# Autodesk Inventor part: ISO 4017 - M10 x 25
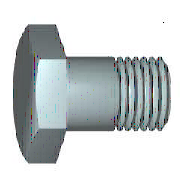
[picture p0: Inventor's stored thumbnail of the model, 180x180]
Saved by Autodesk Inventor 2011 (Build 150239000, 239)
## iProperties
IsCustomPart: 0
Created: 2009-02
Part Number: ISO 4017 - M10 x 25
Material: Stainless Steel, 440C
Description: Hexagon head screws
Document SubType Name: Modeling
Standard: ISO 4017
Designer: 904Chiaki
Standard Revision: Third edition 1999-08-15
Standards Organization: ISO
Language: en-US
Size Designation: M10 x 25
Categories: <MemberInstance><Categories><Category DisplayName="Fasteners" InternalName="e4da775c-781d-43d5-af7c-5136215cf5a6" Mnemonic="FSTN"><Category DisplayName="Bolts"
Density: 7.75 g/cm^3
Mass: 25.8332 g
Surface Area: 15.4943 cm^2
Volume: 3.33332 cm^3
Author: 904Chiaki
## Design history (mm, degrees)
body "Solid1"
workplane "Work Plane1"
revolve "Body" stored, may be unused: angle "d12" = 90 deg
sketch "Sketch2"
  geometry: L1 (0, 9.238)-(8, 4.619); L2 (8, 4.619)-(8, -4.619); L3 (8, -4.619)-(0, -9.238); L4 (0, -9.238)-(-8, -4.619); L5 (-8, -4.619)-(-8, 4.619); L6 (-8, 4.619)-(0, 9.238); 2 further points
  constraints: 12 end point, 1 coincident, 1 vertical, 11 other
  dimensions: "d11" = 16 distance between parallel lines of L5 L2 (= SW)
extrude "Head" join sketch "Sketch2" distance "d3" = 5.8 (= KOH - SD); taper "d4" = 0 deg
revolve "Chamfer1" stored, may be unused: angle "d21" = 90 deg
feature "Thread" dims "d15" = 20.5 (= GEL), "d16" = 0
chamfer "Chamfer2" distance "d6" = 0.92018 (= -0.5 x SPD + 0.5 x GD); stored, may be unused: second distance "d7" = 0.92028 (computed from GUL), angle "d55" = 45 deg
sketch "Sketch1"
  geometry: L1 (0, 7.315)-(0, 5); L2 (4.5, 5)-(25, 5); L3 (25, 5)-(25, 0); L4 (25, 0)-(-0.6, 0); L5 (-5.72, 0)-(30.12, 0) reference; L6 (-0.6, 0)-(-0.6, 7.315); L7 (-0.6, 7.315)-(0, 7.315); L8 (4.5, 5)-(3.58, 5); L9 (3.58, 5)-(0, 5); L10 (0, -1.463)-(0, 8.778) reference
  constraints: 16 end point, 2 collinear, 2 perpendicular, 1 parallel
  dimensions: "d0" = 25 distance between parallel lines of L3 L1 (= NLG); "d1" = 20.5 distance from line of L2.start L3 (= GEL); "d2" = 10 diameter of L2 L4 (= GD); "d9" = 0.6001 distance between parallel lines of L6 L1 (computed from SD); "d10" = 14.63 diameter of L7 L4 (= SD2); "d13" = 0.92028 distance of L2.start L8.end (computed from GAL); "d14" = 10 diameter of L9 L4 (= BDM)
sketch "Sketch4"
  geometry: L1 (-6.4, 8)-(-6.4, 9.238); L2 (-6.4, 9.238)-(-5.686, 9.238); L3 (-5.686, 9.238)-(-6.4, 8); L4 (-7.56, 0)-(0.56, 0) reference; L5 (-0.6, 9.238)-(-6.4, 9.238) reference; L6 (-6.4, 4.619)-(-6.4, 9.238) reference
  constraints: 6 end point, 2 collinear, 1 perpendicular, 1 vertical
  dimensions: "d5" = 30 deg angle of L3 L1 (= ANG1); "d19" = 16 diameter of L1.start L4 (= SW0)
other parameters: "NLG" = 25 [user parameter; used in 1 equation term], "GD" = 10 (= NND) [user parameter; used in 2 equation terms], "BDM" = 10 (= NND) [user parameter; used in 1 equation term], "KOH" = 6.4 [user parameter; used in 1 equation term], "GEL" = 20.5 [user parameter; used in 2 equation terms], "SW" = 16 [user parameter; used in 2 equation terms], "SW0" = 16 (= SW) [user parameter; used in 1 equation term], "SPD" = 8.15965 (= NND - 1.2269 x PTC) [user parameter; used in 1 equation term], "SD2" = 14.63 [user parameter; used in 2 equation terms], "SD" = 0.6 [user parameter; used in 2 equation terms], "ANG1" = 30 deg [user parameter; used in 1 equation term], "GAL" = 0.92018 (= 0.61345 x PTC) [user parameter; used in 1 equation term], "GUL" = 0.92018 (= 0.61345 x PTC) [user parameter; used in 1 equation term], "d8" = 0, "RR" = 0.4 [user parameter], "d57" = 0, "d58" = 0, "TPU" = 6.66667 (computed from PTC) [user parameter], "GD1" = 8.15965 (= THREADDIA - 1.2269 x PTC) [user parameter], "SDH" = 14.63 (= SD2) [user parameter], "SDHG" = 4.5 [user parameter], "TOA" = 30 deg [user parameter], "PTC" = 1.5 [user parameter; used in 5 equation terms], "E0" = 18.48 [user parameter]
